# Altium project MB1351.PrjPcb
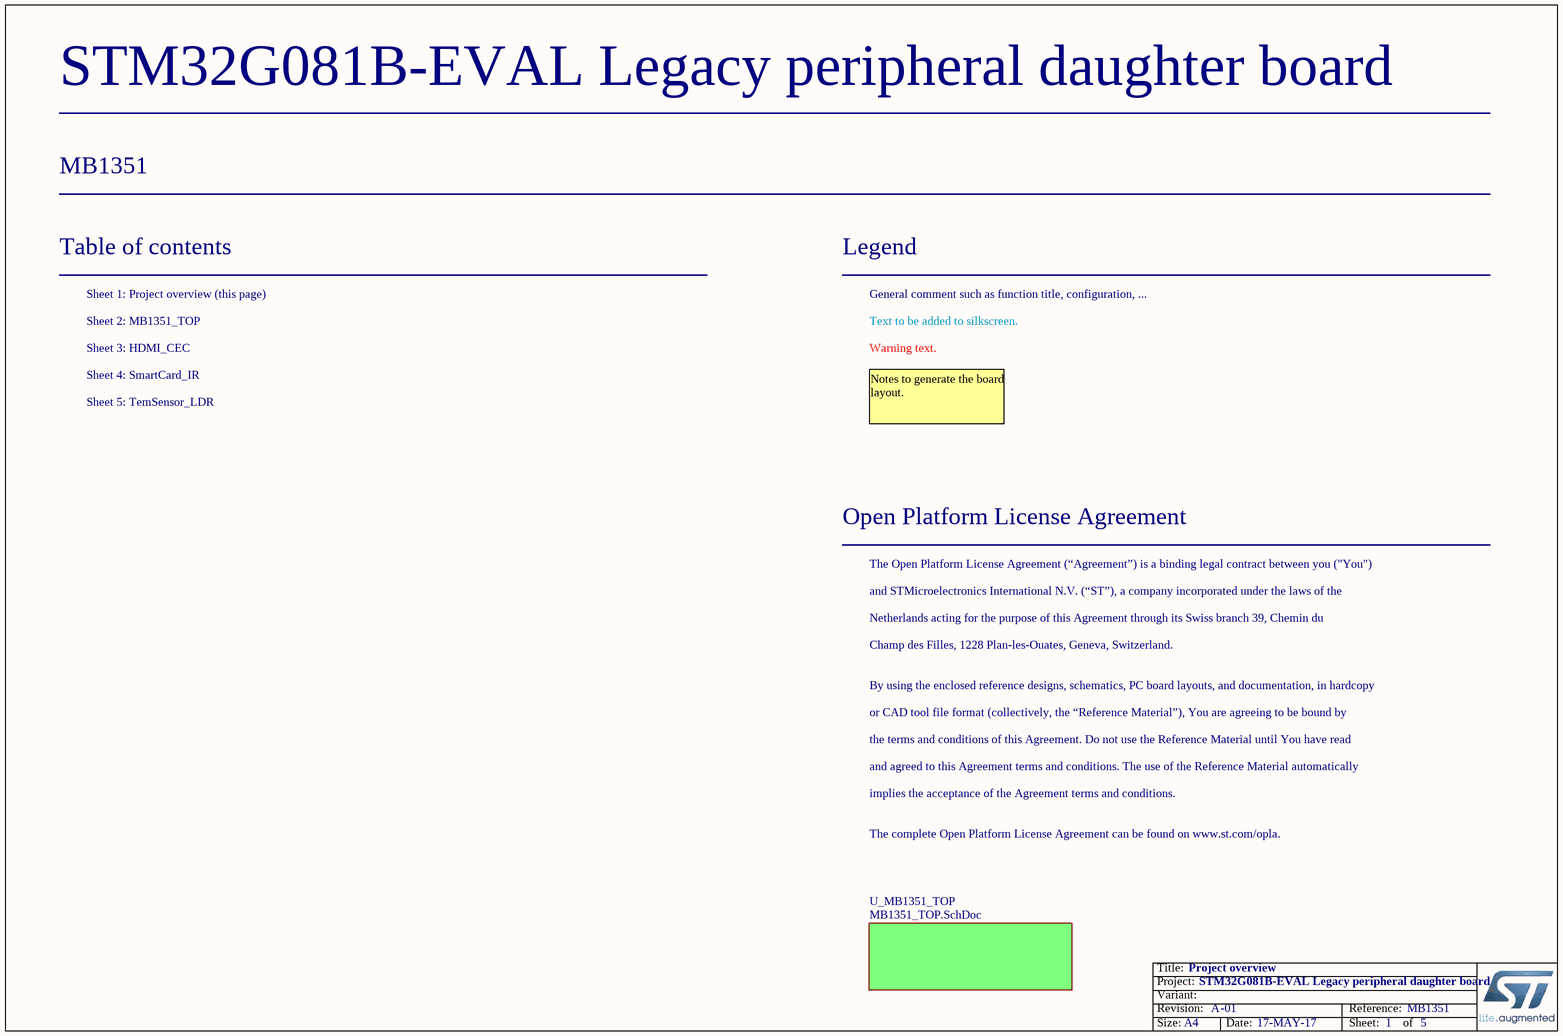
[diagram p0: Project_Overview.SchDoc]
Board_Reference: MB1351; Board_PCB_Revision: A; Board_Name: STM32G081B-EVAL Legacy peripheral daughter board; Board_Document_Date: 17-MAY-17; Board_Assembly_Revision: 01
5 sheets, 66 parts. Net scope: flat (ports and power ports of the same name join across sheets).
Sheets:
  Project_Overview.SchDoc
    U_MB1351_TOP = MB1351_TOP.SchDoc
      U_HDMI_CEC = HDMI_CEC.SchDoc
      U_SmartCard_IR = SmartCard_IR.SchDoc
      U_TemSensor_LDR = TemSensor_LDR.SchDoc

## Sheet Project_Overview.SchDoc: Project overview
size A4; Date: Not used; ApprovedBy: Not used; CheckedBy: Not used; Author: Not used; CompanyName: STMicroelectronics; DrawnBy: Not used; Engineer: Not used; Organization: Not used; Address1: Not used; Address2: Not used; Address3: Not used; Address4: Not used; DocumentNumber: Not used; Revision: Not used; SheetNumber: 1; SheetTotal: 5

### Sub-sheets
U_MB1351_TOP = MB1351_TOP.SchDoc: no entries

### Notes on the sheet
- Table of contents
- Sheet 1: Project overview (this page)
- Legend
- General comment such as function title, configuration, ...
- Sheet 2: MB1351_TOP
- Sheet 3: HDMI_CEC
- Sheet 4: SmartCard_IR
- Text to be added to silkscreen.
- Warning text.
- Sheet 5: TemSensor_LDR
- Notes to generate the board layout.
- Open Platform License Agreement
- The Open Platform License Agreement (“Agreement”) is a binding legal contract between you ("You")
- and STMicroelectronics International N.V. (“ST”), a company incorporated under the laws of the
- Netherlands acting for the purpose of this Agreement through its Swiss branch 39, Chemin du
- Champ des Filles, 1228 Plan-les-Ouates, Geneva, Switzerland.
- By using the enclosed reference designs, schematics, PC board layouts, and documentation, in hardcopy
- or CAD tool file format (collectively, the “Reference Material”), You are agreeing to be bound by
- the terms and conditions of this Agreement. Do not use the Reference Material until You have read
- and agreed to this Agreement terms and conditions. The use of the Reference Material automatically
- implies the acceptance of the Agreement terms and conditions.
- The complete Open Platform License Agreement can be found on www.st.com/opla.

## Sheet MB1351_TOP.SchDoc: MB1351_TOP
size A4; SheetNumber: 2; SheetTotal: 5
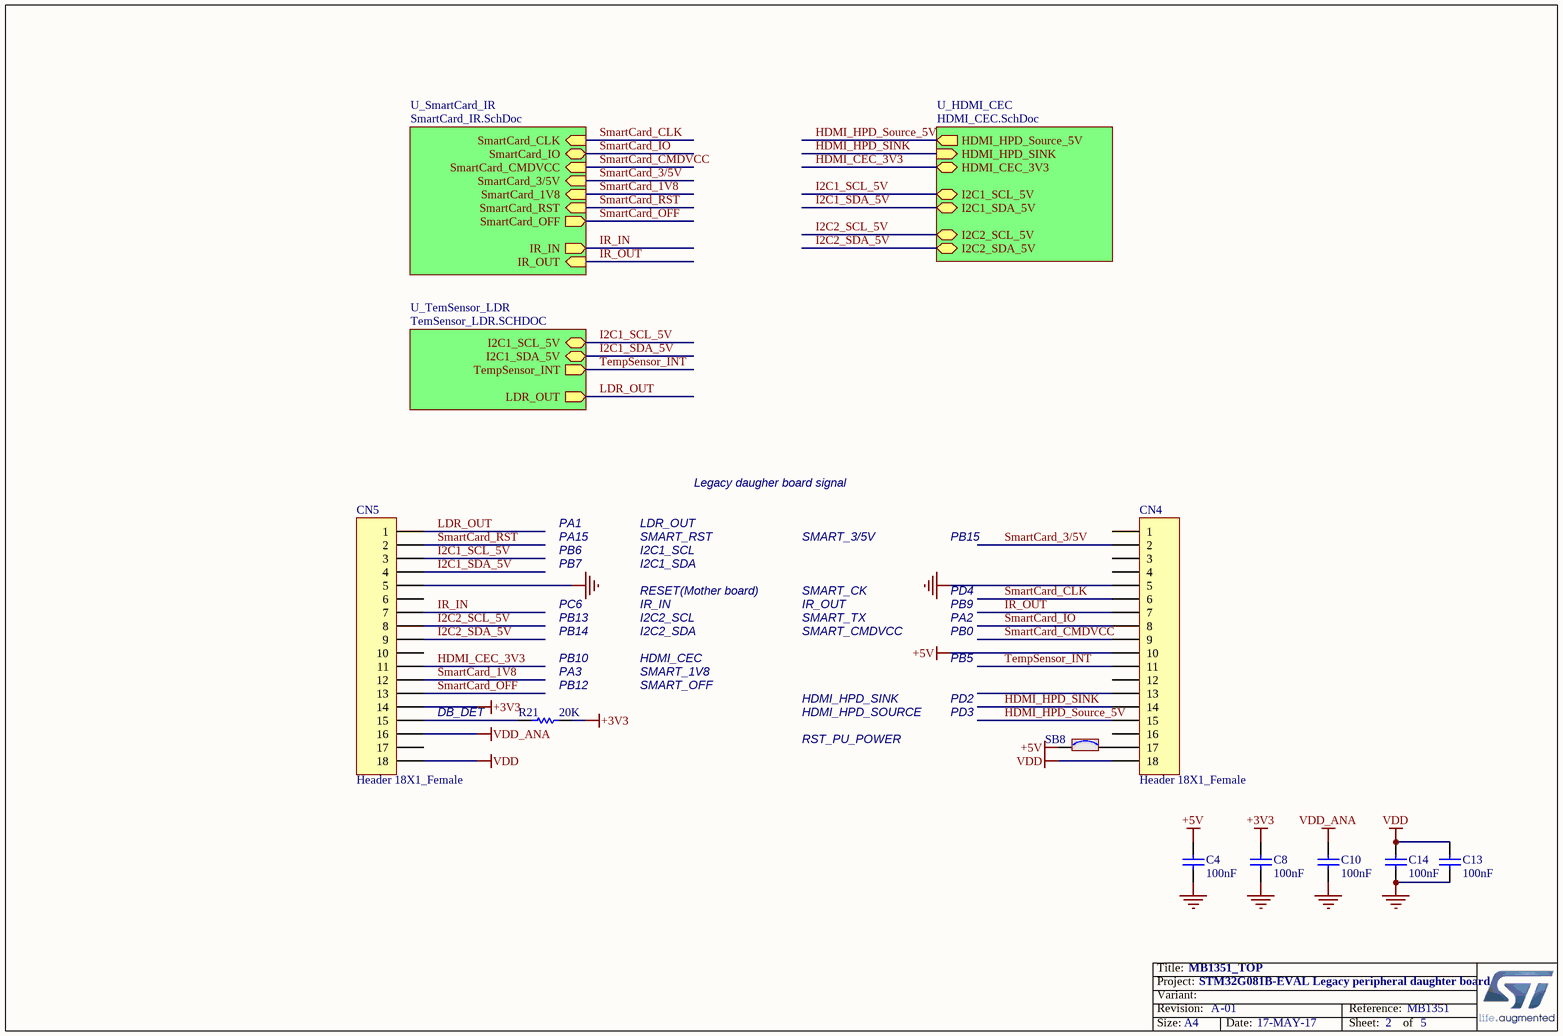
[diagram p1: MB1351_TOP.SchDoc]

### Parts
C4  100nF  [0603C]
C8  100nF  [0603C]
C10  100nF  [0603C]
C13  100nF  [0603C]
C14  100nF  [0603C]
CN4  Header 18X1_Female  [SKT_1X18_2R54]
CN5  Header 18X1_Female  [SKT_1X18_2R54]
R21  20K  [0603R]
SB8  Solder Bridge ON  [SB_0603]  (value not drawn)

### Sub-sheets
U_HDMI_CEC = HDMI_CEC.SchDoc: HDMI_HPD_SINK (in), I2C2_SDA_5V (bidir), I2C2_SCL_5V (bidir), HDMI_CEC_3V3 (bidir), HDMI_HPD_Source_5V (out), I2C1_SCL_5V (bidir), I2C1_SDA_5V (bidir)
U_SmartCard_IR = SmartCard_IR.SchDoc: SmartCard_3/5V (in), SmartCard_IO (bidir), SmartCard_RST (in), SmartCard_CLK (in), SmartCard_OFF (out), SmartCard_CMDVCC (in), IR_OUT (in), IR_IN (out), SmartCard_1V8 (in)
U_TemSensor_LDR = TemSensor_LDR.SCHDOC: I2C1_SCL_5V (bidir), I2C1_SDA_5V (bidir), TempSensor_INT (out), LDR_OUT (out)

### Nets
+3V3: C8.1 CN5.14 R21.1
+5V: C4.1 CN4.10 SB8.1
GND: C4.2 C8.2 C10.2 C13.2 C14.2 CN4.5 CN5.5
VDD: C13.1 C14.1 CN4.18 CN5.18
VDD_ANA: C10.1 CN5.16
HDMI_CEC_3V3: CN5.11 ; sheet U_HDMI_CEC/HDMI_CEC_3V3
HDMI_HPD_SINK: CN4.14 ; sheet U_HDMI_CEC/HDMI_HPD_SINK
HDMI_HPD_Source_5V: CN4.15 ; sheet U_HDMI_CEC/HDMI_HPD_Source_5V
I2C1_SCL_5V: CN5.3 ; sheet U_HDMI_CEC/I2C1_SCL_5V, sheet U_TemSensor_LDR/I2C1_SCL_5V
I2C1_SDA_5V: CN5.4 ; sheet U_HDMI_CEC/I2C1_SDA_5V, sheet U_TemSensor_LDR/I2C1_SDA_5V
I2C2_SCL_5V: CN5.8 ; sheet U_HDMI_CEC/I2C2_SCL_5V
I2C2_SDA_5V: CN5.9 ; sheet U_HDMI_CEC/I2C2_SDA_5V
IR_IN: CN5.7 ; sheet U_SmartCard_IR/IR_IN
IR_OUT: CN4.7 ; sheet U_SmartCard_IR/IR_OUT
LDR_OUT: CN5.1 ; sheet U_TemSensor_LDR/LDR_OUT
SmartCard_1V8: CN5.12 ; sheet U_SmartCard_IR/SmartCard_1V8
SmartCard_3/5V: CN4.2 ; sheet U_SmartCard_IR/SmartCard_3/5V
SmartCard_CLK: CN4.6 ; sheet U_SmartCard_IR/SmartCard_CLK
SmartCard_CMDVCC: CN4.9 ; sheet U_SmartCard_IR/SmartCard_CMDVCC
SmartCard_IO: CN4.8 ; sheet U_SmartCard_IR/SmartCard_IO
SmartCard_OFF: CN5.13 ; sheet U_SmartCard_IR/SmartCard_OFF
SmartCard_RST: CN5.2 ; sheet U_SmartCard_IR/SmartCard_RST
TempSensor_INT: CN4.11 ; sheet U_TemSensor_LDR/TempSensor_INT
NetCN4_17: CN4.17 SB8.2
NetCN5_15: CN5.15 R21.2

Not connected (* = marked no-connect by the designer): CN4 1 3 4 12 13 16; CN5 6 10 17

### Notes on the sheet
- Legacy daugher board signal
- PA1
- PA15
- PB6
- PB7
- LDR_OUT
- SMART_RST
- I2C1_SCL
- I2C1_SDA
- SMART_3/5V
- PB15
- PC6
- PB13
- PB14
- RESET(Mother board)
- IR_IN
- I2C2_SCL
- I2C2_SDA
- SMART_CK
- IR_OUT
- SMART_TX
- SMART_CMDVCC
- PD4
- PB9
- PA2
- PB0
- DB_DET
- PB10
- (near R21) PB12
- (near R21) PA3
- SMART_OFF
- SMART_1V8
- HDMI_CEC
- HDMI_HPD_SINK
- HDMI_HPD_SOURCE
- PB5
- PD2
- PD3
- RST_PU_POWER

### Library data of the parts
C4 C8 C10 C13 C14 = Cap: Capacitor; Value: 10nF
CN4 CN5 = Header 18X1_Female: Header, 18-Pin, Single row, Female
R21 = res1: Resistor; Value: 1K
SB8 = SB_ON: Fitted: YES; Ordered by: Subcon

## Sheet HDMI_CEC.SchDoc: HDMI_CEC
size A4; SheetNumber: 3; SheetTotal: 5
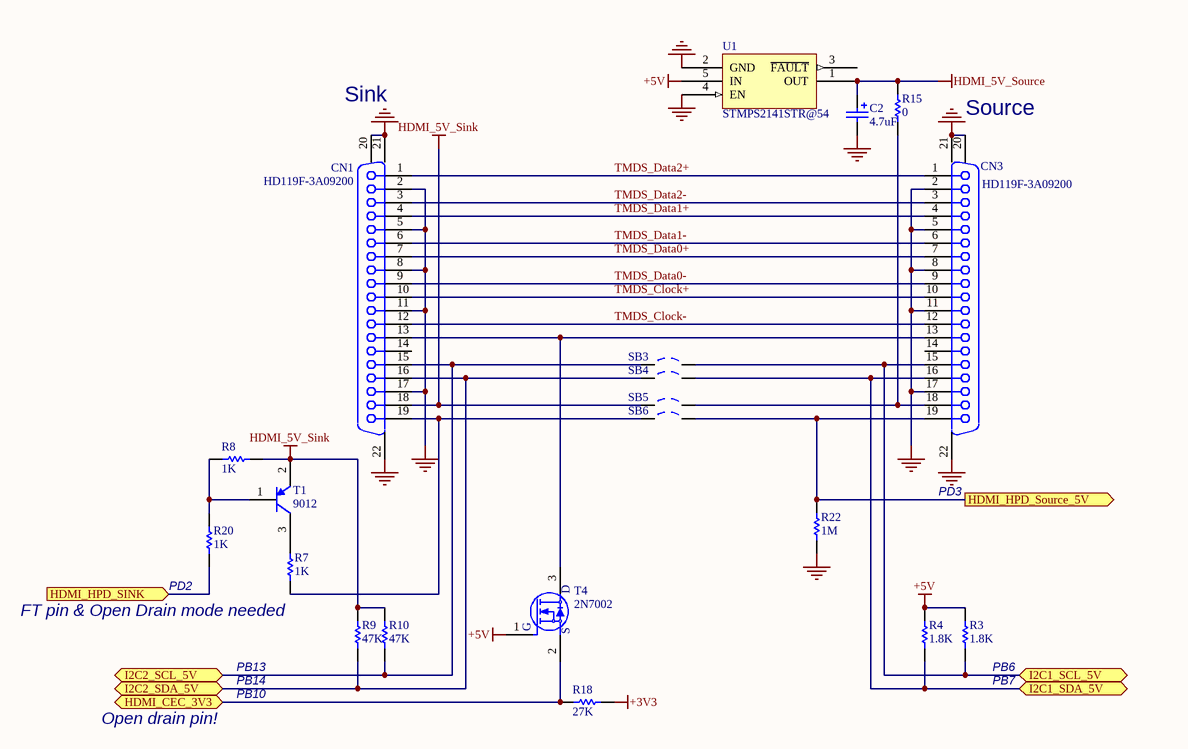
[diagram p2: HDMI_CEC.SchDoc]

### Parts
C2  4.7uF  [TAN-A]
CN1  HD119F-3A09200  [HDMI_19SM_3HD_V_CPT]
CN3  HD119F-3A09200  [HDMI_19SM_3HD_V_CPT]
R3  1.8K  [0603R]
R4  1.8K  [0603R]
R7  1K  [0603R]
R8  1K  [0603R]
R9  47K  [0603R]
R10  47K  [0603R]
R15  0  [0603R]
R18  27K  [0603R]
R20  1K  [0603R]
R22  1M  [0603R]
SB3  Solder Bridge OFF  [SB_0603]  (value not drawn)
SB4  Solder Bridge OFF  [SB_0603]  (value not drawn)
SB5  Solder Bridge OFF  [SB_0603]  (value not drawn)
SB6  Solder Bridge OFF  [SB_0603]  (value not drawn)
T1  9012  [SOT-23]
T4  2N7002  [SOT-23]
U1  STMPS2141STR@54  [SOT23-5]

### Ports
HDMI_CEC_3V3 (bidir), HDMI_HPD_SINK (in), HDMI_HPD_Source_5V (out), I2C1_SCL_5V (bidir), I2C1_SDA_5V (bidir), I2C2_SCL_5V (bidir), I2C2_SDA_5V (bidir)

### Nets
+3V3: R18.2
+5V: R3.2 R4.2 T4.1(G) U1.5(IN)
GND: C2.2 CN1.2 CN1.5 CN1.8 CN1.11 CN1.17 CN1.20(GND) CN1.21(GND) CN1.22(GND) CN3.2 CN3.5 CN3.8 CN3.11 CN3.17 CN3.20(GND) CN3.21(GND) CN3.22(GND) R22.1 U1.2(GND) U1.4(EN)
HDMI_5V_Sink: CN1.18 R8.1 R9.2 R10.2 SB5.1 T1.2(E)
HDMI_5V_Source: C2.1 R15.1 U1.1(OUT)
HDMI_CEC_3V3: R18.1 T4.2(S) ; port HDMI_CEC_3V3
HDMI_HPD_SINK: R20.1 ; port HDMI_HPD_SINK
HDMI_HPD_Source_5V: CN3.19 R22.2 SB6.2 ; port HDMI_HPD_Source_5V
I2C1_SCL_5V: CN3.15 R3.1 SB3.2 ; port I2C1_SCL_5V
I2C1_SDA_5V: CN3.16 R4.1 SB4.2 ; port I2C1_SDA_5V
I2C2_SCL_5V: CN1.15 R10.1 SB3.1 ; port I2C2_SCL_5V
I2C2_SDA_5V: CN1.16 R9.1 SB4.1 ; port I2C2_SDA_5V
TMDS_Clock+: CN1.10 CN3.10
TMDS_Clock-: CN1.12 CN3.12
TMDS_Data0+: CN1.7 CN3.7
TMDS_Data0-: CN1.9 CN3.9
TMDS_Data1+: CN1.4 CN3.4
TMDS_Data1-: CN1.6 CN3.6
TMDS_Data2+: CN1.1 CN3.1
TMDS_Data2-: CN1.3 CN3.3
NetCN1_13: CN1.13 CN3.13 T4.3(D)
NetCN1_19: CN1.19 R7.1 SB6.1
NetCN3_18: CN3.18 R15.2 SB5.2
NetR7_2: R7.2 T1.3(C)
NetR8_2: R8.2 R20.2 T1.1(B)

Not connected (* = marked no-connect by the designer): CN1 14; CN3 14; U1 3(~{FAULT})

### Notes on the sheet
- Sink
- (near CN3) Source
- PD3
- (near R7) FT pin & Open Drain mode needed
- (near R20) PD2
- PB13
- PB14
- (near R3) PB6
- (near R3) PB7
- Open drain pin!
- PB10

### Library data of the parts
C2 = Cap Pol1: Polarized Capacitor (Radial); Value: 47uF
R3 R4 R9 R10 R15 R18 R22 = Res1: Resistor; Value: 1K
R7 R8 R20 = Res1: Resistor
SB3-SB6 = SB_OFF: Fitted: NO; Ordered by: Subcon
T1 = PNP: PNP Bipolar Transistor
U1 = STMPS2141STR

## Sheet SmartCard_IR.SchDoc: SmartCard_IR
size A4; SheetNumber: 4; SheetTotal: 5
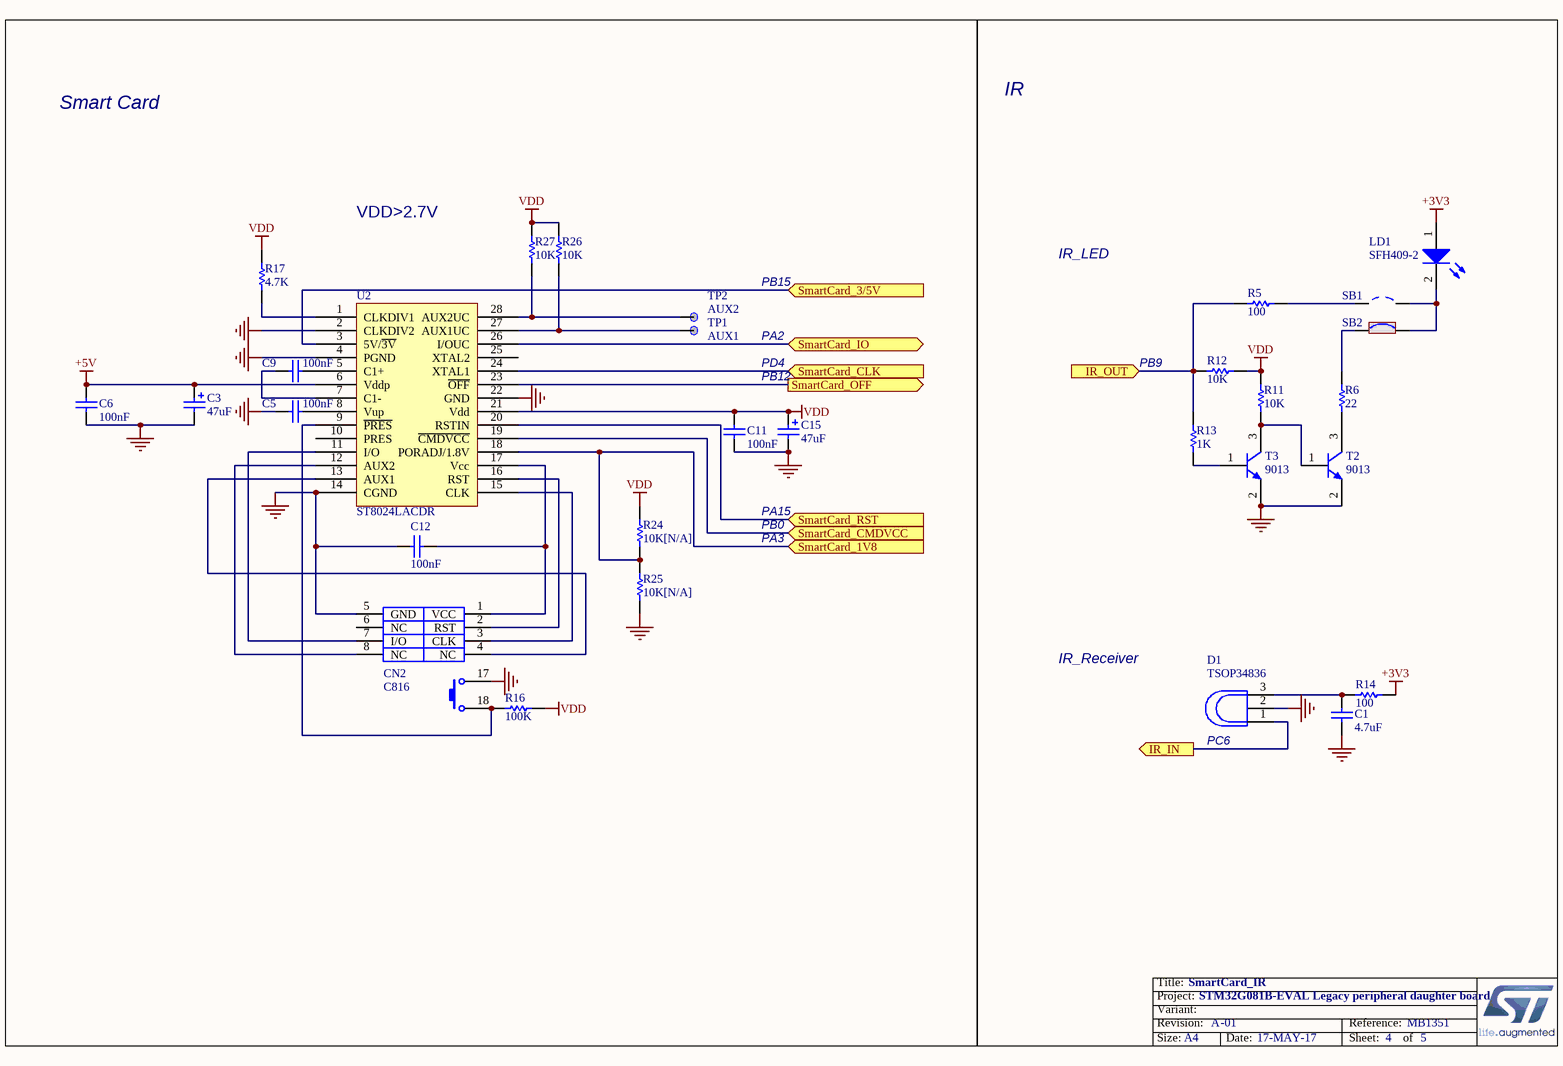
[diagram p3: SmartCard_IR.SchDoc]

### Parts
C1  4.7uF  [0603C]
C3  47uF  [TAN-B]
C5  100nF  [0603C]
C6  100nF  [0603C]
C9  100nF  [0603C]
C11  100nF  [0603C]
C12  100nF  [0603C]
C15  47uF  [TAN-B]
CN2  C816  [sam_c816]
D1  TSOP34836  [IR1_3TH_2R54_REV]
LD1  SFH409-2  [D0_1L]
R5  100  [0603R]
R6  22  [0603R]
R11  10K  [0603R]
R12  10K  [0603R]
R13  1K  [0603R]
R14  100  [0603R]
R16  100K  [0603R]
R17  4.7K  [0603R]
R24  10K[N/A]  [0603R]
R25  10K[N/A]  [0603R]
R26  10K  [0603R]
R27  10K  [0603R]
SB1  Solder Bridge OFF  [SB_0603]  (value not drawn)
SB2  Solder Bridge ON  [SB_0603]  (value not drawn)
T2  9013  [SOT-23]
T3  9013  [SOT-23]
TP1  AUX1  [TP]
TP2  AUX2  [TP]
U2  ST8024LACDR  [SOIC28W_1R27_17R9X10R325]

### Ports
IR_IN (out), IR_OUT (in), SmartCard_1V8 (in), SmartCard_3/5V (in), SmartCard_CLK (in), SmartCard_CMDVCC (in), SmartCard_IO (bidir), SmartCard_OFF (out), SmartCard_RST (in)

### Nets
+3V3: LD1.1(A) R14.2
+5V: C3.1 C6.1 U2.6(Vddp)
GND: C1.2 C3.2 C5.2 C6.2 C11.2 C12.1 C15.2 CN2.5(GND) CN2.17 D1.2(GND) R25.2 T2.2(E) T3.2(E) U2.2(CLKDIV2) U2.4(PGND) U2.14(CGND) U2.22(GND)
VDD: C11.1 C15.1 R11.2 R12.1 R16.1 R17.1 R24.1 R26.1 R27.1 U2.21(Vdd)
IR_IN: D1.1(OUT) ; port IR_IN
IR_OUT: R5.2 R12.2 R13.1 ; port IR_OUT
SmartCard_1V8: R24.2 R25.1 U2.18(PORADJ/1.8V) ; port SmartCard_1V8
SmartCard_3/5V: U2.3(5V/~{3V}) ; port SmartCard_3/5V
SmartCard_CLK: U2.24(XTAL1) ; port SmartCard_CLK
SmartCard_CMDVCC: U2.19(~{CMDVCC}) ; port SmartCard_CMDVCC
SmartCard_IO: U2.26(I/OUC) ; port SmartCard_IO
SmartCard_OFF: U2.23(~{OFF}) ; port SmartCard_OFF
SmartCard_RST: U2.20(RSTIN) ; port SmartCard_RST
NetC1_1: C1.1 D1.3(Vs) R14.1
NetC5_1: C5.1 U2.8(Vup)
NetC9_1: C9.1 U2.7(C1-)
NetC9_2: C9.2 U2.5(C1+)
NetC12_2: C12.2 CN2.1(VCC) U2.17(Vcc)
NetCN2_2: CN2.2(RST) U2.16(RST)
NetCN2_3: CN2.3(CLK) U2.15(CLK)
NetCN2_4: CN2.4(NC) U2.13(AUX1)
NetCN2_7: CN2.7(I/O) U2.11(I/O)
NetCN2_8: CN2.8(NC) U2.12(AUX2)
NetCN2_18: CN2.18 R16.2 U2.9(~{PRES})
NetLD1_2: LD1.2(K) SB1.2 SB2.2
NetR5_1: R5.1 SB1.1
NetR6_1: R6.1 T2.3(C)
NetR6_2: R6.2 SB2.1
NetR11_1: R11.1 T2.1(B) T3.3(C)
NetR13_2: R13.2 T3.1(B)
NetR17_2: R17.2 U2.1(CLKDIV1)
NetR26_2: R26.2 TP1.1 U2.27(AUX1UC)
NetR27_2: R27.2 TP2.1 U2.28(AUX2UC)

Not connected (* = marked no-connect by the designer): CN2 6(NC); U2 10(PRES) 25(XTAL2)

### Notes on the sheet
- Smart Card
- IR
- VDD>2.7V
- IR_LED
- PB15
- PB12
- PD4
- PA2
- PB9
- PA15
- PB0
- PA3
- IR_Receiver
- (near D1) PC6

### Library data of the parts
C1 = Cap: Capacitor; Value: 10nF
C3 C15 = Cap Pol1: Polarized Capacitor (Radial); Value: 100pF
C5 C6 C9 C11 C12 = CAP: Capacitor
CN2 = Smart_card_CN
D1 = TSOP34838
LD1 = LED2: Typical RED, GREEN, YELLOW, AMBER GaAs LED
R5 R6 R11 R12 R14 R16 R17 R24-R27 = Res1: Resistor; Value: 1K
R13 = Res1: Resistor
SB1 = SB_OFF: Fitted: NO; Ordered by: Subcon
SB2 = SB_ON: Fitted: YES; Ordered by: Subcon
T2 T3 = NPN: NPN Bipolar Transistor; Code - JEDEC: TO-226-AA
TP1 TP2 = TP
U2 = ST8024LACTR

## Sheet TemSensor_LDR.SchDoc: TemSensor_LDR
size A4; SheetNumber: 5; SheetTotal: 5
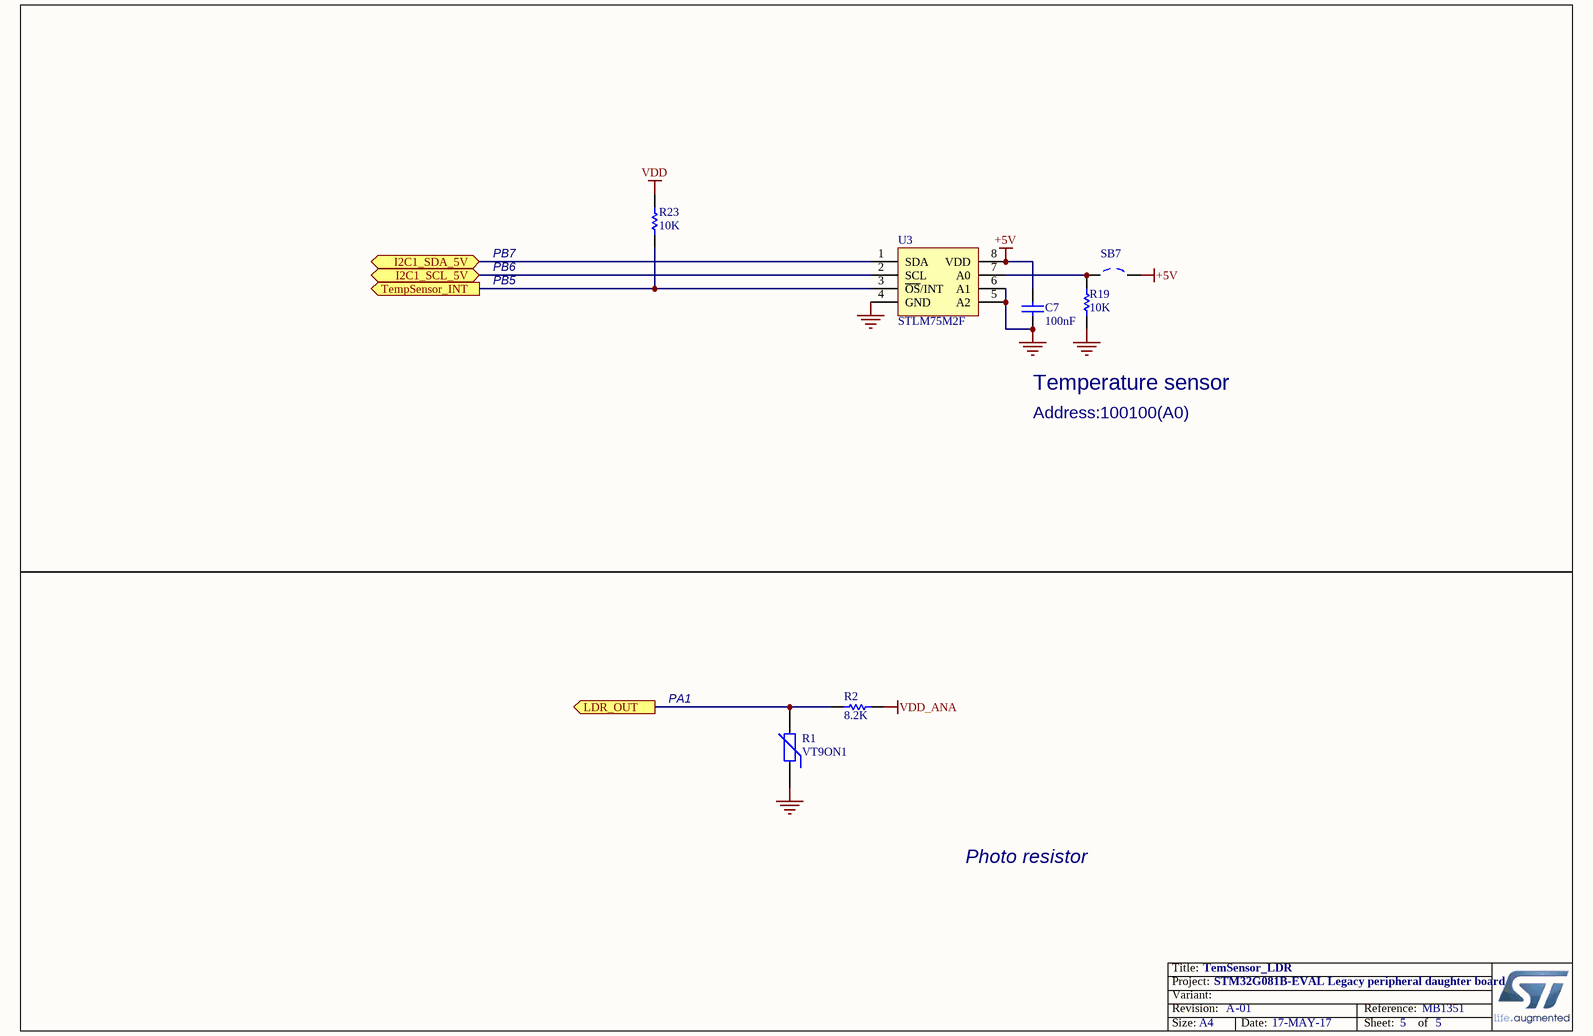
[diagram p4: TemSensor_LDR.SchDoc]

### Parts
C7  100nF  [0603C]
R1  VT9ON1  [PVT901]
R2  8.2K  [0603R]
R19  10K  [0603R]
R23  10K  [0603R]
SB7  Solder Bridge OFF  [SB_0603]  (value not drawn)
U3  STLM75M2F  [SOIC8_1R27_4R9X6]

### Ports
I2C1_SCL_5V (bidir), I2C1_SDA_5V (bidir), LDR_OUT (out), TempSensor_INT (out)

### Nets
+5V: C7.2 SB7.2 U3.8(VDD)
GND: C7.1 R1.1 R19.1 U3.4(GND) U3.5(A2) U3.6(A1)
VDD: R23.2
VDD_ANA: R2.2
I2C1_SCL_5V: U3.2(SCL) ; port I2C1_SCL_5V
I2C1_SDA_5V: U3.1(SDA) ; port I2C1_SDA_5V
LDR_OUT: R1.2 R2.1 ; port LDR_OUT
TempSensor_INT: R23.1 U3.3(~{OS}/INT) ; port TempSensor_INT
NetR19_2: R19.2 SB7.1 U3.7(A0)

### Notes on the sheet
- PB7
- PB6
- PB5
- Temperature sensor
- Address:100100(A0)
- PA1
- Photo resistor

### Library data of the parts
C7 = cap: Capacitor; Value: 100pF
R1 = Res Varistor: Varistor (Voltage-Sensitive Resistor)
R2 R19 R23 = Res1: Resistor; Value: 1K
SB7 = SB_OFF: Fitted: NO; Ordered by: Subcon
U3 = STLM75DW2F

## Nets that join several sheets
+3V3: MB1351_TOP (C8.1 CN5.14 R21.1), HDMI_CEC (R18.2), SmartCard_IR (LD1.1 R14.2)
+5V: MB1351_TOP (C4.1 CN4.10 SB8.1), HDMI_CEC (R3.2 R4.2 T4.1 U1.5), SmartCard_IR (C3.1 C6.1 U2.6), TemSensor_LDR (C7.2 SB7.2 U3.8)
GND: MB1351_TOP (7 pins), HDMI_CEC (20 pins), SmartCard_IR (17 pins), TemSensor_LDR (6 pins)
VDD: MB1351_TOP (C13.1 C14.1 CN4.18 CN5.18), SmartCard_IR (10 pins), TemSensor_LDR (R23.2)
VDD_ANA: MB1351_TOP (C10.1 CN5.16), TemSensor_LDR (R2.2)
I2C1_SCL_5V: HDMI_CEC (CN3.15 R3.1 SB3.2), TemSensor_LDR (U3.2)
I2C1_SDA_5V: HDMI_CEC (CN3.16 R4.1 SB4.2), TemSensor_LDR (U3.1)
